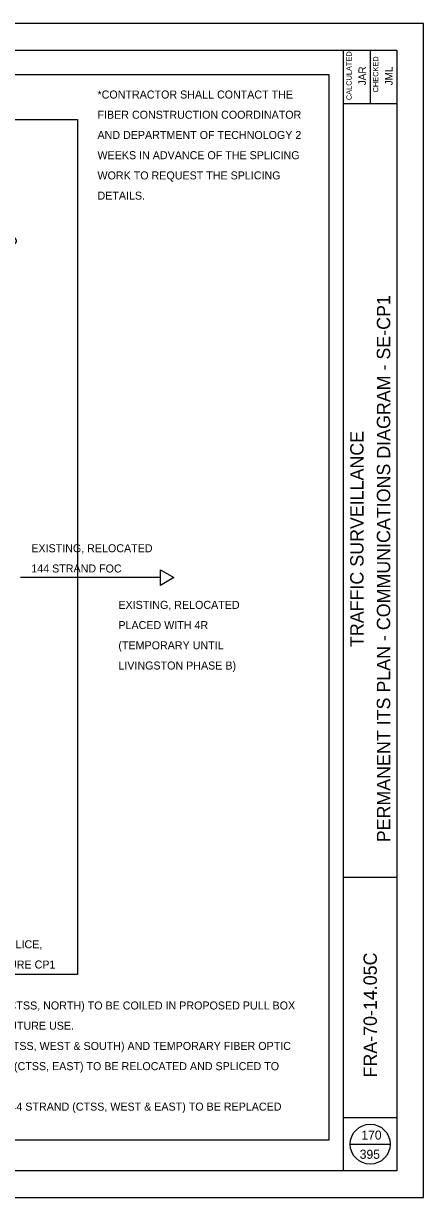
# Model space of a CAD drawing. Extents: x 1805893 to 1833564, y 708898 to 716199.
# Drawn here: x 1832633.1 to 1832783.1, y 713757.9 to 714197.9 of the extents above; entities that cross this region are included whole.
import ezdxf

# ---------------------------------------------------------------- set-up
doc = ezdxf.new("R2010")
doc.units = 0
for name, color, linetype in [('BR_P_Sub_Hidden', 7, 'Continuous'), ('SH_Border', 7, 'Continuous'), ('SH_Cut_Line', 7, 'Continuous'), ('SH_Data', 7, 'Continuous')]:
    doc.layers.add(name, color=color, linetype=linetype)

msp = doc.modelspace()

# ---------------------------------------------------------------- linework, layer by layer
at = {"layer": 'BR_P_Sub_Hidden'}
for points in [[(1832277.01, 714178.75), (1832747.57, 714178.75), (1832747.57, 713779.36), (1832277.01, 713779.36)], [(1832357.86, 714161.88), (1832653.35, 714161.88), (1832653.35, 713841.48), (1832357.86, 713841.48)]]:
    msp.add_lwpolyline(points, close=True, dxfattribs=at)
at = {"layer": 'SH_Border'}
for p, q in [((1832753.13, 713767.91), (1832753.13, 714187.91)), ((1832763.13, 714187.91), (1832763.13, 714167.91)), ((1832753.13, 714167.91), (1832773.13, 714167.91)), ((1832753.13, 713877.91), (1832773.13, 713877.91)), ((1832753.13, 713787.91), (1832773.13, 713787.91))]:
    msp.add_line(p, q, dxfattribs=at)
msp.add_lwpolyline([(1832143.13, 714187.91), (1832773.13, 714187.91), (1832773.13, 713767.91), (1832143.13, 713767.91)], close=True, dxfattribs=at)
at = {"layer": 'SH_Cut_Line'}
msp.add_lwpolyline([(1832103.13, 713757.91), (1832783.13, 713757.91), (1832783.13, 714197.91), (1832103.13, 714197.91)], close=True, dxfattribs=at)
at = {"layer": 'SH_Data'}
for p, q in [((1832684.47, 713987.33), (1832684.47, 713993.13)), ((1832684.47, 713993.13), (1832689.49, 713990.23)), ((1832684.47, 713990.23), (1832631.98, 713990.23)), ((1832689.49, 713990.23), (1832684.47, 713987.33)), ((1832755.63, 713777.91), (1832770.63, 713777.91))]:
    msp.add_line(p, q, dxfattribs=at)
msp.add_circle((1832763.13, 713777.91), 7.5, dxfattribs=at)
msp.add_ellipse((1832587.44, 714116.38), major_axis=(43.05, 0), ratio=0.149566, start_param=5.702888, end_param=10.005075, dxfattribs=at)
msp.add_ellipse((1832587.44, 714116.38), major_axis=(43.05, 0), ratio=0.149566, start_param=5.702888, end_param=10.005075, dxfattribs=at)

# ---------------------------------------------------------------- texts
for s, height, p in [('CALCULATED', 2, (1832756.18, 714169.2)), ('JAR', 2.8, (1832761.53, 714174.74)), ('CHECKED', 2, (1832766.18, 714172.07)), ('JML', 2.8, (1832771.53, 714174.7)), ('PERMANENT ITS PLAN - COMMUNICATIONS DIAGRAM - SE-CP1', 5, (1832770.63, 713891.04)), ('TRAFFIC SURVEILLANCE', 5, (1832760.63, 713964.23)), ('FRA-70-14.05C', 5, (1832765.63, 713802.9))]:
    msp.add_text(s, height=height, rotation=90, dxfattribs=at).set_placement(p)
for s, height, p in [('*CONTRACTOR SHALL CONTACT THE ', 3, (1832660.86, 714169.79)), ('FIBER CONSTRUCTION COORDINATOR ', 3, (1832660.86, 714162.21)), ('AND DEPARTMENT OF TECHNOLOGY 2 ', 3, (1832660.86, 714154.63)), ('WEEKS IN ADVANCE OF THE SPLICING ', 3, (1832660.86, 714147.05)), ('WORK TO REQUEST THE SPLICING ', 3, (1832660.86, 714139.47)), ('DETAILS.', 3, (1832660.86, 714131.89)), ('EXISTING, RELOCATED', 3, (1832636.04, 713999.74)), ('144 STRAND FOC', 3, (1832636.04, 713992.16)), ('EXISTING, RELOCATED', 3, (1832668.7, 713978.52)), ('PLACED WITH 4R', 3, (1832668.7, 713970.95)), ('(TEMPORARY UNTIL', 3, (1832668.7, 713963.37)), ('LIVINGSTON PHASE B)', 3, (1832668.7, 713955.79)), ('PROPOSED DOME, 800 FUSION SPLICE, ', 3, (1832562.6, 713851.31)), ('UNDERGROUND SPLICE ENCLOSURE CP1', 3, (1832562.6, 713843.73)), ('1. PROPOSED FIBER OPTIC CABLE, 144 STRAND (CTSS, NORTH) TO BE COILED IN PROPOSED PULL BOX ', 3, (1832530.8, 713828.38)), ('   AS INDICATED ON THE ITS PLAN SHEETS FOR FUTURE USE.', 3, (1832530.8, 713820.8)), ('2. EXISTING FIBER OPTIC CABLES, 144 STRAND (CTSS, WEST & SOUTH) AND TEMPORARY FIBER OPTIC ', 3, (1832530.8, 713813.22)), ('   CABLE PLACED WITH PROJECT 4R, 144 STRAND (CTSS, EAST) TO BE RELOCATED AND SPLICED TO ', 3, (1832530.8, 713805.64)), ('3. EXISTING/TEMPORARY FIBER OPTIC CABLES, 144 STRAND (CTSS, WEST & EAST) TO BE REPLACED ', 3, (1832530.8, 713790.48)), ('170', 3.4, (1832759.82, 713779.61)), ('395', 3.4, (1832759.21, 713772.41))]:
    msp.add_text(s, height=height, dxfattribs=at).set_placement(p)

doc.saveas('drawing.dxf')
